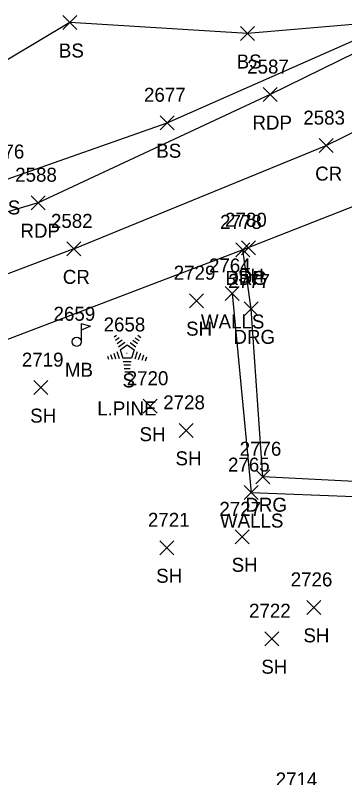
# Model space of a CAD drawing. Extents: x 1609623 to 1616187, y 756677 to 762826.
# Drawn here: x 1610488.8 to 1610535.9, y 761921.9 to 762030.9 of the extents above; entities that cross this region are included whole.
import ezdxf

# ---------------------------------------------------------------- set-up
doc = ezdxf.new("R2010")
doc.units = 0
for name, color, linetype in [('L_A', 7, 'Continuous'), ('L_C', 7, 'Continuous'), ('L_I', 7, 'Continuous'), ('L_TIC', 7, 'Continuous'), ('LELB', 7, 'Continuous'), ('LMB', 7, 'Continuous'), ('LTC', 7, 'Continuous'), ('LWS', 7, 'Continuous'), ('P_A', 7, 'Continuous'), ('P_I', 7, 'Continuous'), ('P_TIC', 7, 'Continuous'), ('PET', 7, 'Continuous'), ('PRC', 7, 'Continuous'), ('R_A', 7, 'Continuous'), ('R_I', 7, 'Continuous'), ('R_TIC', 7, 'Continuous'), ('RDG', 7, 'Continuous')]:
    doc.layers.add(name, color=color, linetype=linetype)

msp = doc.modelspace()

# ---------------------------------------------------------------- linework, layer by layer
at = {"layer": 'L_TIC'}
for points in [[(1610495.6, 762028.88), (1610497.6, 762030.88)], [(1610497.6, 762028.88), (1610495.6, 762030.88)], [(1610521, 762027.31), (1610523, 762029.31)], [(1610523, 762027.31), (1610521, 762029.31)], [(1610509.51, 762014.56), (1610511.51, 762016.56)], [(1610511.51, 762014.56), (1610509.51, 762016.56)], [(1610521.12, 761996.7), (1610523.12, 761998.7)], [(1610523.12, 761996.7), (1610521.12, 761998.7)], [(1610518.79, 761990.16), (1610520.79, 761992.16)], [(1610520.79, 761990.16), (1610518.79, 761992.16)], [(1610513.72, 761989.13), (1610515.72, 761991.13)], [(1610515.72, 761989.13), (1610513.72, 761991.13)], [(1610491.45, 761976.7), (1610493.45, 761978.7)], [(1610493.45, 761976.7), (1610491.45, 761978.7)], [(1610507.07, 761974.05), (1610509.07, 761976.05)], [(1610509.07, 761974.05), (1610507.07, 761976.05)], [(1610512.21, 761970.6), (1610514.21, 761972.6)], [(1610514.21, 761970.6), (1610512.21, 761972.6)], [(1610521.51, 761961.7), (1610523.51, 761963.7)], [(1610523.51, 761961.7), (1610521.51, 761963.7)], [(1610520.23, 761955.38), (1610522.23, 761957.38)], [(1610522.23, 761955.38), (1610520.23, 761957.38)], [(1610509.46, 761953.81), (1610511.46, 761955.81)], [(1610511.46, 761953.81), (1610509.46, 761955.81)], [(1610530.48, 761945.3), (1610532.48, 761947.3)], [(1610532.48, 761945.3), (1610530.48, 761947.3)], [(1610524.47, 761940.82), (1610526.47, 761942.82)], [(1610526.47, 761940.82), (1610524.47, 761942.82)]]:
    msp.add_lwpolyline(points, dxfattribs=at)
at = {"layer": 'LELB'}
msp.add_lwpolyline([(1610593.52, 762087.9), (1610586.3, 762069.19), (1610572.23, 762053.77), (1610574.3, 762048.25), (1610559.77, 762040.18), (1610540.96, 762029.92), (1610522, 762028.31), (1610496.6, 762029.88), (1610470.76, 762014.43), (1610459.21, 762003.19), (1610487.51, 762007.45), (1610510.51, 762015.56), (1610540.51, 762028.79)], dxfattribs=at)
at = {"layer": 'LMB'}
for p, q in [((1610498.24, 761986.86), (1610499.54, 761986.48)), ((1610498.25, 761984.27), (1610498.25, 761986.87)), ((1610498.25, 761985.96), (1610499.53, 761986.47)), ((1610497.59, 761984.26), (1610497.59, 761984.26))]:
    msp.add_line(p, q, dxfattribs=at)
msp.add_circle((1610497.59, 761984.26), 0.656, dxfattribs=at)
at = {"layer": 'LTC'}
for p, q in [((1610502.93, 761984.94), (1610503.29, 761985.2)), ((1610506.33, 761985.18), (1610506.75, 761984.88)), ((1610503.14, 761984.48), (1610503.67, 761984.86)), ((1610503.35, 761984.01), (1610504.06, 761984.52)), ((1610503.56, 761983.54), (1610504.44, 761984.18)), ((1610505.22, 761984.14), (1610506.03, 761983.55)), ((1610505.59, 761984.49), (1610506.27, 761983.99)), ((1610505.96, 761984.83), (1610506.51, 761984.43)), ((1610503.79, 761983.09), (1610504.8, 761983.82)), ((1610503.79, 761983.09), (1610504.18, 761981.9)), ((1610504.8, 761983.82), (1610505.8, 761983.1)), ((1610505.8, 761983.1), (1610505.41, 761981.9)), ((1610501.97, 761982.22), (1610502.12, 761981.75)), ((1610502.42, 761982.44), (1610502.63, 761981.79)), ((1610502.88, 761982.65), (1610503.15, 761981.82)), ((1610503.33, 761982.87), (1610503.66, 761981.85)), ((1610505.41, 761981.9), (1610504.18, 761981.9)), ((1610506.23, 761982.83), (1610505.9, 761981.79)), ((1610506.68, 761982.58), (1610506.39, 761981.69)), ((1610507.12, 761982.33), (1610506.89, 761981.6)), ((1610507.57, 761982.08), (1610507.38, 761981.5)), ((1610505.37, 761981.4), (1610504.22, 761981.4)), ((1610505.28, 761980.9), (1610504.3, 761980.9)), ((1610505.2, 761980.4), (1610504.37, 761980.4)), ((1610505.12, 761979.9), (1610504.44, 761979.9))]:
    msp.add_line(p, q, dxfattribs=at)
at = {"layer": 'LWS'}
msp.add_lwpolyline([(1610519.79, 761991.16), (1610522.51, 761962.7), (1610547.01, 761961.77), (1610547.97, 761985.38)], dxfattribs=at)
at = {"layer": 'P_TIC'}
for points in [[(1610524.2, 762018.58), (1610526.2, 762020.58)], [(1610526.2, 762018.58), (1610524.2, 762020.58)], [(1610532.22, 762011.29), (1610534.22, 762013.29)], [(1610534.22, 762011.29), (1610532.22, 762013.29)], [(1610491.06, 762003.13), (1610493.06, 762005.13)], [(1610493.06, 762003.13), (1610491.06, 762005.13)], [(1610496.17, 761996.53), (1610498.17, 761998.53)], [(1610498.17, 761996.53), (1610496.17, 761998.53)], [(1610520.33, 761996.39), (1610522.33, 761998.39)], [(1610522.33, 761996.39), (1610520.33, 761998.39)]]:
    msp.add_lwpolyline(points, dxfattribs=at)
at = {"layer": 'PET'}
for points in [[(1610577.62, 762049.8), (1610559.53, 762036.47), (1610525.2, 762019.58), (1610492.06, 762004.13), (1610473.85, 761998.71), (1610441.74, 761998.52)], [(1610581.57, 762022.41), (1610544.98, 762006.7), (1610521.33, 761997.39), (1610475.41, 761979.89)]]:
    msp.add_lwpolyline(points, dxfattribs=at)
at = {"layer": 'PRC'}
for points in [[(1610497.17, 761997.53), (1610533.22, 762012.29), (1610581.21, 762035.95)], [(1610497.17, 761997.53), (1610478.04, 761990.3)]]:
    msp.add_lwpolyline(points, dxfattribs=at)
at = {"layer": 'R_TIC'}
for points in [[(1610520.33, 761996.39), (1610522.33, 761998.39)], [(1610522.33, 761996.39), (1610520.33, 761998.39)], [(1610521.49, 761987.96), (1610523.49, 761989.96)], [(1610523.49, 761987.96), (1610521.49, 761989.96)], [(1610523.19, 761963.97), (1610525.19, 761965.97)], [(1610525.19, 761963.97), (1610523.19, 761965.97)]]:
    msp.add_lwpolyline(points, dxfattribs=at)
at = {"layer": 'RDG'}
msp.add_lwpolyline([(1610544.98, 762006.7), (1610544.09, 761988.41), (1610545.65, 761963.86), (1610524.19, 761964.97), (1610522.49, 761988.96), (1610521.33, 761997.39)], dxfattribs=at)

# ---------------------------------------------------------------- texts
at = {"layer": 'L_A'}
for s, p in [('BS', (1610495.04, 762024.88)), ('BS', (1610520.44, 762023.31)), ('BS', (1610508.95, 762010.56)), ('BS', (1610485.95, 762002.45)), ('SH', (1610520.61, 761992.7)), ('WALLS', (1610515.33, 761986.16)), ('SH', (1610513.21, 761985.13)), ('MB', (1610495.9, 761979.26)), ('S', (1610504.13, 761977.73)), ('SH', (1610490.94, 761972.7)), ('SH', (1610506.56, 761970.05)), ('SH', (1610511.7, 761966.6)), ('WALLS', (1610518.05, 761957.7)), ('SH', (1610519.72, 761951.38)), ('SH', (1610508.94, 761949.81)), ('SH', (1610529.97, 761941.3)), ('SH', (1610523.96, 761936.82))]:
    msp.add_text(s, height=2, dxfattribs=at).set_placement(p)
at = {"layer": 'L_C'}
msp.add_text('L.PINE', height=2, dxfattribs=at).set_placement((1610500.52, 761973.73))
at = {"layer": 'L_I'}
for s, p in [('2677', (1610507.2, 762018.56)), ('2676', (1610484.15, 762010.45)), ('2780', (1610518.78, 762000.7)), ('2764', (1610516.48, 761994.16)), ('2729', (1610511.45, 761993.13)), ('2659', (1610494.28, 761987.26)), ('2658', (1610501.43, 761985.73)), ('2719', (1610489.75, 761980.7)), ('2720', (1610504.73, 761978.05)), ('2728', (1610509.95, 761974.6)), ('2765', (1610519.2, 761965.7)), ('2727', (1610517.97, 761959.38)), ('2721', (1610507.76, 761957.81)), ('2726', (1610528.16, 761949.3)), ('2722', (1610522.21, 761944.82)), ('2714', (1610526.01, 761920.7))]:
    msp.add_text(s, height=2, dxfattribs=at).set_placement(p)
at = {"layer": 'LTC'}
msp.add_text('.', height=1.04, rotation=270, dxfattribs=at).set_placement((1610504.68, 761982.84))
at = {"layer": 'P_A'}
for s, p in [('RDP', (1610522.69, 762014.58)), ('CR', (1610531.65, 762007.29)), ('RDP', (1610489.55, 761999.13)), ('CR', (1610495.6, 761992.53)), ('RDP', (1610518.82, 761992.39))]:
    msp.add_text(s, height=2, dxfattribs=at).set_placement(p)
at = {"layer": 'P_I'}
for s, p in [('2587', (1610521.94, 762022.58)), ('2583', (1610529.96, 762015.29)), ('2588', (1610488.8, 762007.13)), ('2582', (1610493.91, 762000.53)), ('2778', (1610518.07, 762000.39))]:
    msp.add_text(s, height=2, dxfattribs=at).set_placement(p)
at = {"layer": 'R_A'}
for p in [(1610518.82, 761992.39), (1610519.98, 761983.96), (1610521.68, 761959.97)]:
    msp.add_text('DRG', height=2, dxfattribs=at).set_placement(p)
at = {"layer": 'R_I'}
for s, p in [('2778', (1610518.07, 762000.39)), ('2777', (1610519.23, 761991.96)), ('2776', (1610520.87, 761967.97))]:
    msp.add_text(s, height=2, dxfattribs=at).set_placement(p)

doc.saveas('drawing.dxf')
